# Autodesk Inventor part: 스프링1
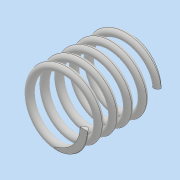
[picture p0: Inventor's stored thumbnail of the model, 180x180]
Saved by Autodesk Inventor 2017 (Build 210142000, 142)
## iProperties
Part Number: 스프링1
Material: 일반
Document SubType Name: Modeling
Designer: MRC
Density: 1 g/cm^3
Appearance: 기본값
Author: MRC
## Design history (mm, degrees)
sketch "스케치1"
  geometry: L1 (0, 0)-(0, 20.5); L2 (0, 0)-(8.5, 0); L3 (0, 20.5)-(8.5, 20.5); C1 r 1 at (8.5, 0)
  constraints: 6 end point, 1 centre point, 1 coincident, 1 horizontal, 1 vertical, 1 vertical alignment
  dimensions: "d0" = 20.5 distance of L1.start L1.end (derived); "d1" = 17 diameter of L2.end L1; "d2" = 2 diameter of C1
feature "코일1" pitch "d3" = 10; turns "d5" = 5; dims "d4" = 20.5 (= d0), "d6" = 0, angle "d7" = 90 deg, angle "d8" = 90 deg, "d9" = 0, "d10" = 0
sketch "스케치2"
  geometry: L1 (20.5, 17.5)-(0, 17.5); L2 (0, 17.5)-(0, -17.5); L3 (0, -17.5)-(20.5, -17.5); L4 (20.5, -17.5)-(20.5, 17.5); 2 further points
  constraints: 8 end point, 2 parallel, 1 coincident, 1 horizontal, 1 midpoint, 1 perpendicular
  dimensions: "d11" = 20.5 distance of L2.end L3.end (= d0); "d12" = 35 distance between parallel lines of L1 L3
extrude "돌출2" sketch "스케치2" stored distance "d15" = 0; taper "d16" = 0 deg
node "솔리드1"
